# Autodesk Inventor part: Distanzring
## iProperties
Shininess: 20.0
Angle Display Precision: 2
Document Length Units: 11269
Document Angle Units: 11279
Document Time Units: 11290
Document Mass Units: 11283
Document Length Units Precision: 3
Document Angle Units Precision: 2
Created: 2003-02
Part Number: Distanzring
Material: S275JR
Document SubType Name: Modellieren
Designer: Administrator
Density: 0.0
Volumn: 0.0
Area: 0.0
PropertySet Name: Model Information
Control State: 0
Master: False
Checked Out: False
Author: Administrator
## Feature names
1. Grundkörper [Revolution]
